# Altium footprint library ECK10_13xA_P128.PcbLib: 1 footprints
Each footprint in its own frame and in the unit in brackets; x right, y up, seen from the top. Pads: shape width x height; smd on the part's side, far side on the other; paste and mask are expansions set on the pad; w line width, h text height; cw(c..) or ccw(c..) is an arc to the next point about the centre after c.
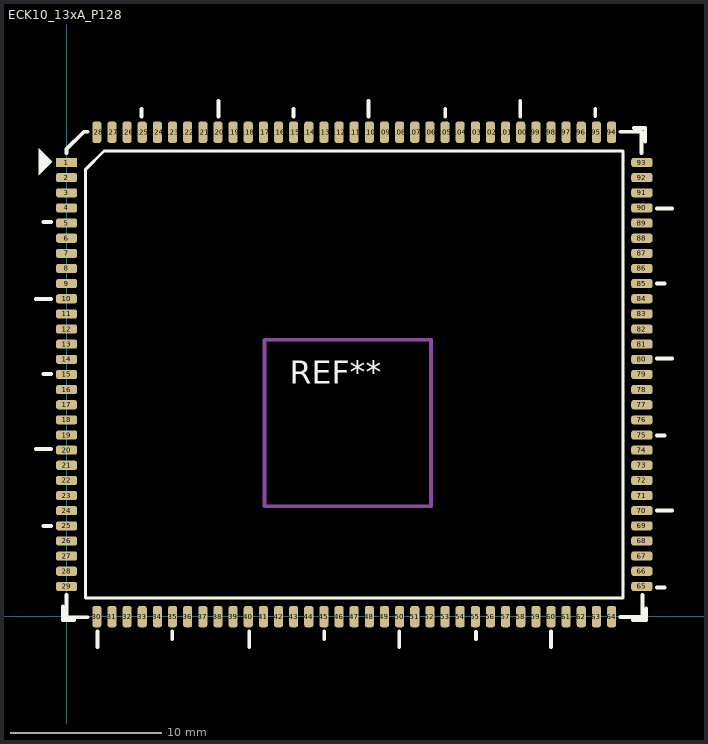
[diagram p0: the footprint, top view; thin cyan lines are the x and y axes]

## ECK10_13xA_P128 [mm]
pads (128):
  rect 1.4x0.6 smd: 1(0,29.972)
  rrect50% 1.4x0.6 smd: 2(0,28.972) 3(0,27.972) 4(0,26.972) 5(0,25.972) 6(0,24.972) 7(0,23.972) 8(0,22.972) 9(0,21.972) 10(0,20.972) 11(0,19.972) 12(0,18.972) 13(0,17.972) 14(0,16.972) 15(0,15.972) 16(0,14.972) 17(0,13.972) 18(0,12.972) 19(0,11.972) 20(0,10.972) 21(0,9.972) 22(0,8.972) 23(0,7.972) 24(0,6.972) 25(0,5.972) 26(0,4.972) 27(0,3.972) 28(0,2.972) 29(0,1.972) 65(38,1.972) 66(38,2.972) 67(38,3.972) 68(38,4.972) 69(38,5.972) 70(38,6.972) 71(38,7.972) 72(38,8.972) 73(38,9.972) 74(38,10.972) 75(38,11.972) 76(38,12.972) 77(38,13.972) 78(38,14.972) 79(38,15.972) 80(38,16.972) 81(38,17.972) 82(38,18.972) 83(38,19.972) 84(38,20.972) 85(38,21.972) 86(38,22.972) 87(38,23.972) 88(38,24.972) 89(38,25.972) 90(38,26.972) 91(38,27.972) 92(38,28.972) 93(38,29.972)
  rrect50% 0.6x1.4 smd: 30(2,-0.028) 31(3,-0.028) 32(4,-0.028) 33(5,-0.028) 34(6,-0.028) 35(7,-0.028) 36(8,-0.028) 37(9,-0.028) 38(10,-0.028) 39(11,-0.028) 40(12,-0.028) 41(13,-0.028) 42(14,-0.028) 43(15,-0.028) 44(16,-0.028) 45(17,-0.028) 46(18,-0.028) 47(19,-0.028) 48(20,-0.028) 49(21,-0.028) 50(22,-0.028) 51(23,-0.028) 52(24,-0.028) 53(25,-0.028) 54(26,-0.028) 55(27,-0.028) 56(28,-0.028) 57(29,-0.028) 58(30,-0.028) 59(31,-0.028) 60(32,-0.028) 61(33,-0.028) 62(34,-0.028) 63(35,-0.028) 64(36,-0.028) 94(36,31.972) 95(35,31.972) 96(34,31.972) 97(33,31.972) 98(32,31.972) 99(31,31.972) 100(30,31.972) 101(29,31.972) 102(28,31.972) 103(27,31.972) 104(26,31.972) 105(25,31.972) 106(24,31.972) 107(23,31.972) 108(22,31.972) 109(21,31.972) 110(20,31.972) 111(19,31.972) 112(18,31.972) 113(17,31.972) 114(16,31.972) 115(15,31.972) 116(14,31.972) 117(13,31.972) 118(12,31.972) 119(11,31.972) 120(10,31.972) 121(9,31.972) 122(8,31.972) 123(7,31.972) 124(6,31.972) 125(5,31.972) 126(4,31.972) 127(3,31.972) 128(2,31.972)
Top Overlay:
  region: -1.841,29.146 -0.953,30.035 -1.841,30.924
  lines w0.2: 1.235,1.207 36.765,1.207 36.765,30.737 2.47,30.737 1.235,29.502 1.235,1.207
  lines w0.254: -2.032,11.049 -1.016,11.049 ; -2.032,20.955 -1.016,20.955 ; -1.524,5.969 -1.024,5.969 ; -1.524,16.002 -1.024,16.002 ; -1.516,26.035 -1.016,26.035 ; -0.254,0.635 -0.254,-0.254 0.508,-0.254 ; 0,1.397 0,-0.064 1.397,-0.064 ; 0,30.607 0,30.861 1.143,32.004 1.397,32.004 ; 2.032,-2.032 2.032,-1.016 ; 4.953,33.02 4.953,33.52 ; 6.985,-1.516 6.985,-1.016 ; 10.033,33.02 10.033,34.036 ; 12.065,-2.032 12.065,-1.016 ; 14.986,33.02 14.986,33.52 ; 17.018,-1.516 17.018,-1.016 ; 19.939,33.02 19.939,34.036 ; 21.971,-2.032 21.971,-1.016 ; 25.019,33.02 25.019,33.52 ; 27.051,-1.524 27.051,-1.024 ; 29.972,33.02 29.972,34.036 ; 32.004,-2.032 32.004,-1.016 ; 34.925,33.028 34.925,33.528 ; 36.576,-0.045 38.04,-0.045 38.04,1.397 ; 36.576,32.004 37.973,32.004 37.973,30.607 ; 37.401,-0.254 38.291,-0.254 38.291,0.508 ; 37.465,32.258 38.227,32.258 38.227,31.369 ; 38.989,1.905 39.489,1.905 ; 38.989,6.985 40.005,6.985 ; 38.989,11.938 39.489,11.938 ; 38.989,17.018 40.005,17.018 ; 38.989,21.971 39.489,21.971 ; 38.989,26.924 40.005,26.924
  text "REF**" at 14.732,15.367 h1.52
Mechanical 1:
  lines w0.254: 13.081,7.262 24.081,7.262 24.081,18.262 13.081,18.262 13.081,7.262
